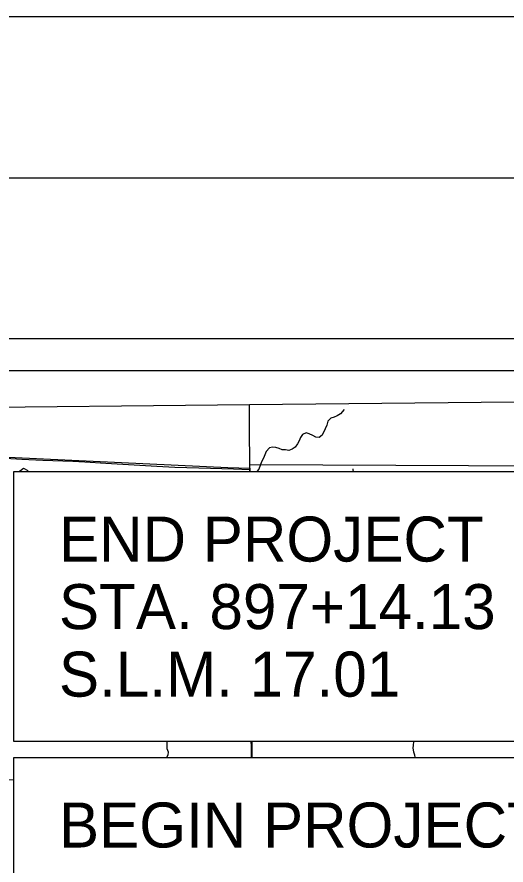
# Model space of a CAD drawing. Extents: x 0 to 34, y 0 to 22.
# Drawn here: x 28.163 to 29.684, y 19.362 to 22 of the extents above; entities that cross this region are included whole.
import ezdxf

# ---------------------------------------------------------------- set-up
doc = ezdxf.new("R2010")
doc.units = 0
for name, color, linetype in [('GM_X_County', 7, 'Continuous'), ('GM_X_County_Road', 7, 'Continuous'), ('GM_X_Minor_River', 7, 'Continuous'), ('GM_X_Section', 7, 'Continuous'), ('GM_X_Township_Road', 7, 'Continuous'), ('SC_Scratch1', 7, 'Continuous'), ('SH_Border', 7, 'Continuous'), ('SH_Cut_Line', 7, 'Continuous'), ('SH_Data', 7, 'Continuous'), ('SH_Text', 7, 'Continuous')]:
    doc.layers.add(name, color=color, linetype=linetype)

msp = doc.modelspace()

# ---------------------------------------------------------------- linework, layer by layer
at = {"layer": 'GM_X_County'}
for points in [[(28.8862, 20.7941), (27.8891, 20.7835), (26.8843, 20.7634), (25.88, 20.7414), (25.1253, 20.7174), (23.8668, 20.6853), (23.5167, 20.6789)], [(30.3167, 20.8109), (30.0181, 20.8047), (28.8862, 20.7941)]]:
    msp.add_lwpolyline(points, dxfattribs=at)
at = {"layer": 'GM_X_County_Road'}
msp.add_line((28.8876, 20.5861), (28.8875, 20.5925), dxfattribs=at)
for points in [[(28.8875, 20.5925), (28.8875, 20.6158), (28.8866, 20.7122), (28.8864, 20.7935)], [(28.8922, 19.6968), (28.8919, 19.7324), (28.8917, 19.7461)]]:
    msp.add_lwpolyline(points, dxfattribs=at)
at = {"layer": 'GM_X_Minor_River'}
for points in [[(29.1802, 20.7796), (29.1689, 20.7661), (29.1593, 20.759), (29.1498, 20.755), (29.1391, 20.7524), (29.1303, 20.7426), (29.1271, 20.7305), (29.1213, 20.7192), (29.1127, 20.6996), (29.1028, 20.6921), (29.0925, 20.693), (29.0827, 20.698), (29.0722, 20.7038), (29.062, 20.7066), (29.0513, 20.7017), (29.0451, 20.6916), (29.0405, 20.6818), (29.0354, 20.6719), (29.0285, 20.6622), (29.0189, 20.6554), (29.0083, 20.6521), (28.9977, 20.6534), (28.9878, 20.6542), (28.978, 20.6578), (28.9678, 20.6605), (28.958, 20.6618), (28.9485, 20.6596), (28.9385, 20.6483), (28.9342, 20.6385), (28.9295, 20.6275), (28.9237, 20.6166), (28.9194, 20.6049), (28.9147, 20.5932), (28.9088, 20.5861)], [(28.1722, 20.5861), (28.1739, 20.5894), (28.1834, 20.5965), (28.1947, 20.5907), (28.1986, 20.5861)], [(28.6282, 19.7461), (28.6288, 19.744), (28.6291, 19.7338), (28.6286, 19.7243), (28.633, 19.714), (28.6321, 19.7041), (28.6281, 19.6968)], [(29.3962, 19.7461), (29.3962, 19.746), (29.3953, 19.7354), (29.3941, 19.7256), (29.3966, 19.7149), (29.3991, 19.705), (29.4, 19.6968)]]:
    msp.add_lwpolyline(points, dxfattribs=at)
at = {"layer": 'GM_X_Section'}
for p, q in [((28.8934, 19.7461), (28.8938, 19.6968)), ((28.8938, 19.6968), (28.8934, 19.7461))]:
    msp.add_line(p, q, dxfattribs=at)
for points in [[(28.1535, 19.6259), (27.9, 19.6399), (27.892, 20.6425), (28.8187, 20.5991), (28.8871, 20.5965), (28.8872, 20.5861)], [(28.8872, 20.5861), (28.8871, 20.5965), (28.8869, 20.6082), (30.0212, 20.6024), (30.0362, 19.5914), (29.8322, 19.5929)]]:
    msp.add_lwpolyline(points, dxfattribs=at)
at = {"layer": 'GM_X_Township_Road'}
for points in [[(27.8919, 20.6403), (27.9082, 20.6396), (27.9425, 20.6383), (27.9766, 20.6367), (28.0007, 20.6353), (28.0585, 20.6322), (28.1785, 20.6248), (28.2437, 20.6218), (28.3369, 20.6181), (28.3742, 20.6163), (28.4394, 20.6125), (28.5977, 20.6027), (28.6536, 20.5998), (28.7281, 20.5972), (28.8369, 20.5942), (28.8875, 20.5925)], [(29.2093, 20.5861), (29.2089, 20.5919), (29.2091, 20.595)]]:
    msp.add_lwpolyline(points, dxfattribs=at)
at = {"layer": 'SC_Scratch1'}
msp.add_lwpolyline([(23.5167, 20.6789), (23.5167, 15.3175), (30.3167, 15.3175), (30.3167, 20.8109), (30.0181, 20.8047), (28.8862, 20.7941), (27.8891, 20.7835), (26.8843, 20.7634), (25.88, 20.7414), (25.1253, 20.7174), (23.8668, 20.6853)], close=True, dxfattribs=at)
at = {"layer": 'SH_Border'}
msp.add_lwpolyline([(1.5, 21.5), (33.5, 21.5), (33.5, 0.5), (1.5, 0.5)], close=True, dxfattribs=at)
at = {"layer": 'SH_Cut_Line'}
msp.add_lwpolyline([(0, 0), (34, 0), (34, 22), (0, 22)], close=True, dxfattribs=at)
at = {"layer": 'SH_Data'}
for points in [[(23.4167, 21), (30.4167, 21), (30.4167, 14), (23.4167, 14)], [(23.5167, 20.9), (30.3167, 20.9), (30.3167, 15.3175), (23.5167, 15.3175)], [(28.1535, 20.5861), (29.7961, 20.5861), (29.7961, 19.7461), (28.1535, 19.7461)], [(28.1535, 19.6968), (29.8322, 19.6968), (29.8322, 18.8568), (28.1535, 18.8568)]]:
    msp.add_lwpolyline(points, close=True, dxfattribs=at)

# ---------------------------------------------------------------- texts
at = {"layer": 'SH_Text'}
for s, p in [('END PROJECT', (28.2935, 20.3061)), ('STA. 897+14.13', (28.2935, 20.0961)), ('S.L.M. 17.01', (28.2935, 19.8861)), ('BEGIN PROJECT', (28.2935, 19.4168))]:
    msp.add_text(s, height=0.14, dxfattribs=at).set_placement(p)

doc.saveas('drawing.dxf')
